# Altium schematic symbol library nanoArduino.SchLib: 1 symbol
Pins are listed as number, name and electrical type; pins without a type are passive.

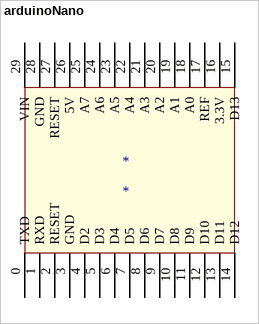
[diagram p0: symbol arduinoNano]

## arduinoNano
designator *
footprint Arduino nano (arduino nano)
pins: 0 TXD, 1 RXD, 2 RESET, 3 GND, 4 D2, 5 D3, 6 D4, 7 D5, 8 D6, 9 D7, 10 D8, 11 D9, 12 D10, 13 D11, 14 D12, 15 D13, 16 3.3V, 17 REF, 18 A0, 19 A1, 20 A2, 21 A3, 22 A4, 23 A5, 24 A6, 25 A7, 26 5V, 27 RESET, 28 GND, 29 VIN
